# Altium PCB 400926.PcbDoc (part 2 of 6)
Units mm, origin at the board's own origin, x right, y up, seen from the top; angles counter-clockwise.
Board outline 148.5 x 63.5 mm, 4 copper layers (Top Layer, Mid-Layer 1, Mid-Layer 2, Bottom Layer), stack 1.514 mm thick; 311 components, 281 nets, 1495 pads, 2232 vias.
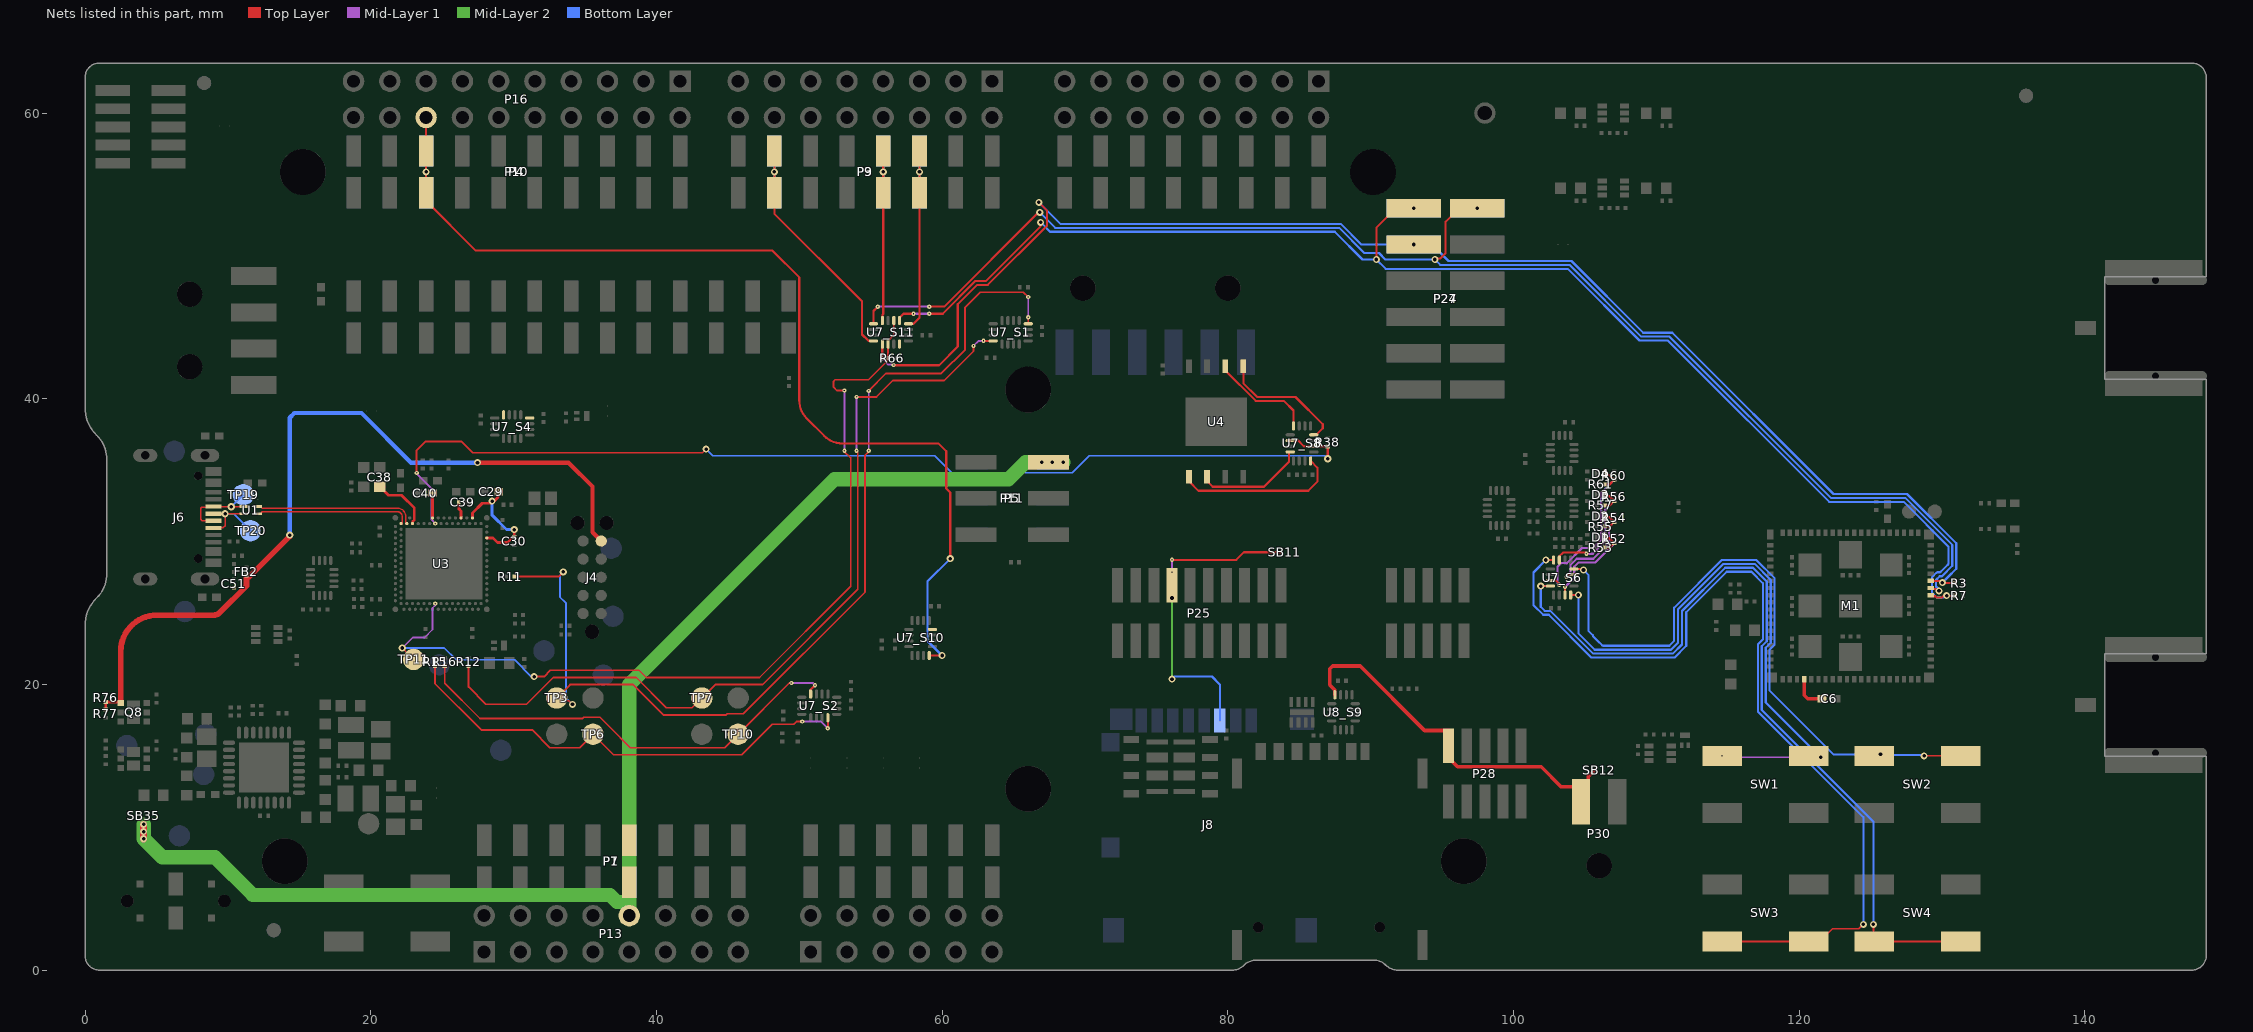
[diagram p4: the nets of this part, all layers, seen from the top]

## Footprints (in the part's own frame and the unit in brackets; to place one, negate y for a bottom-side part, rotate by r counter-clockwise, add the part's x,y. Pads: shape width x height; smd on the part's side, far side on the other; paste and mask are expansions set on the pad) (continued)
SOCKET_1x6_SMD [mm] "Socket, 2.54mm, SMD"
  rect 1.02x2.19 smd: 1(0,-1.465) 1(0,1.465) 2(2.54,-1.465) 2(2.54,1.465) 3(5.08,-1.465) 3(5.08,1.465) 4(7.62,-1.465) 4(7.62,1.465) 5(10.16,-1.465) 5(10.16,1.465) 6(12.7,1.465) 6(12.7,-1.465)
  silkscreen extent -1.27,-1.27 13.97,1.27, body extent -1.27,-2.29 13.97,2.29, height 7.47
SOCKET_1x8_SMD [mm] "Socket, 2.54mm, SMD"
  rect 1.02x2.19 smd: 1(0,-1.465) 1(0,1.465) 2(2.54,-1.465) 2(2.54,1.465) 3(5.08,-1.465) 3(5.08,1.465) 4(7.62,-1.465) 4(7.62,1.465) 5(10.16,-1.465) 5(10.16,1.465) 6(12.7,1.465) 6(12.7,-1.465) 7(15.24,-1.465) 7(15.24,1.465) 8(17.78,-1.465) 8(17.78,1.465)
  silkscreen extent -1.27,-1.27 19.05,1.27, body extent -1.27,-2.29 19.05,2.29, height 7.47
SOCKET_1x10_SMD [mm] "Socket, 2.54mm, SMD"
  rect 1.02x2.19 smd: 1(0,1.465) 1(0,-1.465) 2(2.54,-1.465) 2(2.54,1.465) 3(5.08,-1.465) 3(5.08,1.465) 4(7.62,-1.465) 4(7.62,1.465) 5(10.16,-1.465) 5(10.16,1.465) 6(12.7,-1.465) 6(12.7,1.465) 7(15.24,-1.465) 7(15.24,1.465) 8(17.78,-1.465) 8(17.78,1.465) 9(20.32,-1.465) 9(20.32,1.465) 10(22.86,-1.465) 10(22.86,1.465)
  silkscreen extent -1.27,-1.27 24.13,1.27, body extent -1.27,-2.29 24.13,2.29, height 7.47
SOCKET_2x3_SMD-2.54mm-NC [mm] "Socket, 2.54mm, SMD"
  rect 1.02x2.22 smd: 1(2.54,-2.825) 2(2.54,2.825) 3(0,-2.825) 4(0,2.825) 5(-2.54,-2.825) 6(-2.54,2.825)
  silkscreen extent -3.81,-3.3 3.81,2.54
SOCKET_2x6_SMD-2.54mm#1 [mil]
  rect 50x150 smd: 1(-250,-87.5) 2(-250,87.5) 3(-150,-87.5) 4(-150,87.5) 5(-50,-87.5) 6(-50,87.5) 7(50,-87.5) 8(50,87.5) 9(150,-87.5) 10(150,87.5) 11(250,-87.5) 12(250,87.5)
  silkscreen extent -310,-127 300,100, body extent -300,-138 300,139, height 290
SOCKET_2x6_SMD-2.54mm#2 [mil] "Board-Board Conn, Header, 4-way, 2-row"
  rect 50x150 smd: 1(-250,87.5) 2(-250,-87.5) 3(-150,87.5) 4(-150,-87.5) 5(-50,87.5) 6(-50,-87.5) 7(50,87.5) 8(50,-87.5) 9(150,87.5) 10(150,-87.5) 11(250,87.5) 12(250,-87.5)
  silkscreen extent -310,-100 300,127
SODFL35X40-2N [mm] "SODFL, 2-Leads, Body 0,60x0,35mm, IPC Medium Density"
  rect 0.25x0.6 smd: 1(-0.325,0) 3(0.325,0)
  body extent -0.53,-0.33 0.53,0.33, height 0.4
Solderbridge [mil]
  round 1 smd paste-99999: 1(-13.78,0) 2(13.78,0)
  Top Layer region: -7.49,19.36 -15.76,15.74 -21.55,8.8 -23.62,0 -23.62,0 -21.55,-8.79 -15.76,-15.74 -7.49,-19.36 -7.49,-19.36 -6.18,-19.31 -5.02,-18.71 -4.22,-17.68 -3.94,-16.4 -3.94,-16.4 -3.94,16.4 -4.22,17.68 -5.02,18.71 -6.18,19.31 -7.49,19.36
  Top Layer region: 7.49,-19.36 15.76,-15.74 21.55,-8.8 23.62,0 23.62,0 21.55,8.79 15.76,15.74 7.49,19.36 7.49,19.36 6.18,19.31 5.02,18.71 4.22,17.68 3.94,16.4 3.94,16.4 3.94,-16.4 4.22,-17.68 5.02,-18.71 6.18,-19.31 7.49,-19.36
Solderbridge_Shorted [mil]
  round 1 smd paste-99999: 1(-13.78,0) 2(13.78,0)
  Top Layer region: -4.92,3.94 -4.92,-3.94 4.92,-3.94 4.92,3.94
  Top Layer region: -7.49,19.36 -15.76,15.74 -21.55,8.8 -23.62,0 -23.62,0 -21.55,-8.79 -15.76,-15.74 -7.49,-19.36 -7.49,-19.36 -6.18,-19.31 -5.02,-18.71 -4.22,-17.68 -3.94,-16.4 -3.94,-16.4 -3.94,16.4 -4.22,17.68 -5.02,18.71 -6.18,19.31 -7.49,19.36
  Top Layer region: 7.49,-19.36 15.76,-15.74 21.55,-8.8 23.62,0 23.62,0 21.55,8.79 15.76,15.74 7.49,19.36 7.49,19.36 6.18,19.31 5.02,18.71 4.22,17.68 3.94,16.4 3.94,16.4 3.94,-16.4 4.22,-17.68 5.02,-18.71 6.18,-19.31 7.49,-19.36
Solderbridge_Shorted_Power [mil]
  round 1 smd paste-99999: 1(-13.84,0.21) 2(13.72,0.21)
  Top Layer region: -4.92,9.84 4.92,9.84 4.92,-9.84 -4.92,-9.84
  Top Layer region: 7.43,-19.16 15.71,-15.53 21.49,-8.59 23.56,0.21 23.56,0.21 21.49,9 15.71,15.94 7.43,19.57 7.43,19.57 6.12,19.52 4.96,18.92 4.16,17.89 3.88,16.61 3.88,16.61 3.88,-16.2 4.16,-17.47 4.96,-18.51 6.12,-19.11 7.43,-19.16
  Top Layer region: -7.54,19.57 -15.82,15.94 -21.61,9 -23.68,0.21 -23.68,0.21 -21.61,-8.59 -15.82,-15.53 -7.54,-19.16 -7.54,-19.16 -6.24,-19.11 -5.08,-18.51 -4.28,-17.47 -4,-16.2 -3.99,-16.2 -3.99,16.61 -4.28,17.89 -5.08,18.92 -6.24,19.52 -7.54,19.57
SON50P210X160X65_HS-9N [mm] "SON, 8-Leads, Body 2.10x1.60mm, Pitch 0.50mm, Thermal Pad 1.70x0.4mm, IPC Medium Density"
  rect 0.7x0.25 smd mask+0.05: 1(-0.725,0.75) 2(-0.725,0.25) 3(-0.725,-0.25) 4(-0.725,-0.75) 5(0.725,-0.75) 6(0.725,-0.25) 7(0.725,0.25) 8(0.725,0.75)
  rect 0.4x1.7 smd paste-2 mask+0.05: 9(0,0)
  rect 0.3x0.75 on Top Paste: ""(0,0.425) ""(0,-0.425)
  silkscreen extent -1.26,1.2 -1.16,1.26, body extent -0.85,-1.1 0.85,1.1, height 0.65
SON127P600X90_HS-8N [mm] "SON, 8-Leads, Body 5.00x6.00mm, Pitch 1.27mm, IPC Medium Density"
  rect 1.5x0.35 smd paste-1.27: 0(-0.95,-1.73) 0(-0.95,1.73) 0(0.95,-1.73) 0(0.95,1.73)
  rect 1.5x0.7 smd paste-1.27: 0(-0.95,-0.635) 0(-0.95,0.635) 0(0.95,-0.635) 0(0.95,0.635)
  rect 1.1x0.5 smd paste-1.27: 1(-2.75,1.905) 2(-2.75,0.635) 3(-2.75,-0.635) 4(-2.75,-1.905) 5(2.75,-1.905) 6(2.75,-0.635) 7(2.75,0.635) 8(2.75,1.905)
  silkscreen extent -3.6,-2.58 3.08,2.72, body extent -3,-2.5 3,2.5, height 0.65
SON127P800X80_HS-9N [mm] "SON, 8-Leads, Body 6.00x8.00mm, Pitch 1.27mm, Thermal Pad 4.30x3.40mm, IPC Medium Density"
  rect 0.95x0.4 smd: 1(-3.87,1.905) 2(-3.87,0.635) 3(-3.87,-0.635) 4(-3.87,-1.905) 5(3.87,-1.905) 6(3.87,-0.635) 7(3.87,0.635) 8(3.87,1.905)
  rect 3.4x4.3 smd paste-1.7: 9(0,0)
  silkscreen extent -4.52,-3.18 4.18,3.52, body extent -4.05,-3.05 4.05,3.05, height 0.8
SOTFL50P162X60-6N [mm] "SOTFL, 6-Leads, Body 1.60x1.63mm, Pitch 0.50mm, IPC Medium Density"
  rect 0.65x0.35 smd: 1(-0.775,0.5) 2(-0.775,0) 3(-0.775,-0.5) 4(0.775,-0.5) 5(0.775,0) 6(0.775,0.5)
  silkscreen extent -0.9,-0.82 0.05,1.35, body extent -0.81,-0.85 0.81,0.85, height 0.6
TC2050-IDC-NLFP [mil]
  round 39 hole 39 unplated: 0(-150,0) 0(150,-40) 0(150,40)
  round 31 smd paste-196.85: 1(-100,-25) 2(-50,-25) 3(0,-25) 4(50,-25) 5(100,-25) 6(100,25) 7(50,25) 8(0,25) 9(-50,25) 10(-100,25)
  Top Layer pour cut-out: -100,25 -100,-25 100,-25 100,25
TESTPAD-TH [mm]
  round 1.5 hole 1: 1(0,0)
TP_SMD_D1.0mm [mm] "Test point - pad 1.0mm"
  round 1 smd paste-5: 1(0,0)
TP_SMD_D1.5mm [mm] "Test point - pad 1.5mm"
  round 1.5 smd paste-5: 1(0,0)
  body extent -0.75,-0.75 0.75,0.75, height 0.05
UFDFN50P120X250X55-8N [mm]
  round 0.025 smd: 1(-0.5,0.75) 4(-0.5,-0.75) 5(0.5,-0.75) 8(0.5,0.75)
  rect 0.6x0.2 smd: 2(-0.5,0.25) 3(-0.5,-0.25) 6(0.5,-0.25) 7(0.5,0.25)
  Top Layer region: -0.2,0.65 -0.8,0.65 -0.8,0.85 -0.4,0.85 -0.4,1.05 -0.2,1.05
  Top Layer region: 0.4,0.85 0.8,0.85 0.8,0.65 0.2,0.65 0.2,1.05 0.4,1.05
  Top Layer region: -0.2,-1.05 -0.4,-1.05 -0.4,-0.85 -0.8,-0.85 -0.8,-0.65 -0.2,-0.65
  Top Layer region: 0.8,-0.85 0.4,-0.85 0.4,-1.05 0.2,-1.05 0.2,-0.65 0.8,-0.65
  silkscreen extent -1.08,1.21 -0.95,1.33, body extent -0.6,-1.25 0.6,1.25, height 0.6
WEEE_3x4.5mm [mm]
  silkscreen extent -1.47,-2.7 1.47,1.71
XQFN40P180X260X50-16N [mm] "QFN, 16-Leads, Body 1.80x2.60mm, Pitch 0.40mm, IPC Medium Density"
  oval 0.65x0.22 smd paste-0.02 mask+0.04: 1(-0.825,0.6) 2(-0.825,0.2) 3(-0.825,-0.2) 4(-0.825,-0.6) 9(0.825,-0.6) 10(0.825,-0.2) 11(0.825,0.2) 12(0.825,0.6)
  oval 0.22x0.65 smd paste-0.02 mask+0.04: 5(-0.6,-1.225) 6(-0.2,-1.225) 7(0.2,-1.225) 8(0.6,-1.225) 13(0.6,1.225) 14(0.2,1.225) 15(-0.2,1.225) 16(-0.6,1.225)
  body extent -0.91,-1.31 0.91,1.31, height 0.55

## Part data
C1 C2: library part C0201-1µ0-10V-X5R-GRM033R61A105ME15, "Capacitor, X5R, ±20%, 10V", Manufacturer=Murata, Manufacturer Part Number=GRM033R61A105ME15, Part number IPS=N.A., Part number NEMS=100200545, Supplier Part Number 1=490-13226-1-ND
C3 C7: library part C0603-10µ-10V-X6S-GRM188C81A106MA73, "Capacitor, Ceramic, 10µF 10V X6S 0603,±20%", Manufacturer=Murata, Manufacturer Part Number=GRM188C81A106MA73, Part number IPS=N.A., Part number NEMS=100200520, Supplier Part Number 1=490-7197-2-ND
C4 C8 C10 C24 C25 C26 C27 C31 C32 C33 C34 C39 C42 C43 C51 C52_S1 C52_S2 C52_S3 C52_S4 C52_S5 C52_S6 C52_S8 C52_S10 C52_S11 C53_S7 C53_S9 C62: library part C0201-100n, "Capacitor, X5R, ±10%, 100nF, 16V", Manufacturer=N.A., Part number IPS="00000001248, 00000002505", Part number NEMS=100200078, Part number Norautron=262071862
C5 C6: library part C0402-4µ7-10V-X5R, "Capacitor, X5R, 10V", Manufacturer=Murata, Manufacturer Part Number=GRM155R61A475MEAAD, Part number IPS=N.A., Part number NEMS=100200415, Supplier Part Number 1=490-14306-1-ND
C9: library part C0402-1µ0-16V-X5R, "Capacitor, Ceramic, X5R, ±10%, 16V", Manufacturer=Murata, Manufacturer Part Number=GRT155R61C105KE01D, Part number IPS=N.A., Part number NEMS=100200452, Supplier Part Number 1=490-12255-1-ND
C11 C12: library part C0201-39p, "Capacitor, NP0, ±1%, 25V", Manufacturer=Murata, Manufacturer Part Number=GRM0335C1E390FA01D, Part number IPS=00000001668, Part number NEMS=100200039, Part number Norautron=N.A.
C19 C49: library part C0201-N.C., "Not mounted", Manufacturer=N.A., Part number NEMS=100200001
C28 C29 C35 C36 C40 C64: library part C0402-1µ0-10V-X5R, "Capacitor, Ceramic, X5R, ±10%, 10V", Manufacturer=N.A., Part number NEMS=100200482
C30: library part C0201-2n2, "Capacitor, X7R, ±10%, 10V", Manufacturer=N.A., Part number IPS=00000001778, Part number NEMS=100200060, Part number Norautron=26470002
C37 C38 C58: library part C0603-4µ7-10V-X5R, "Capacitor, Ceramic, X5R, ±10%, 10V", Manufacturer=N.A., Part number NEMS=100200479, Part number Norautron=262081761
C41 C48 C50: library part C0201-10n, "Capacitor, X7R, ±10%, 10nF, 10V", Manufacturer=N.A., Part number IPS=00000003480, Part number NEMS=100200067, Part number Norautron=26621779
C44 C45 C46 C47: library part C0201-1µ0, "Capacitor, X5R, ±10%", Manufacturer=N.A., Part number IPS=00000001723, Part number NEMS=100200084, Supplier Part Number 1=1276-6795-1-ND
C54: library part C0603-1µ0-10V-X5R, "Capacitor, Ceramic, 1.0µF 10V X5R 0603,±10%", Manufacturer=N.A., Part number NEMS=100200528
C55 C56 C57 C59 C60: library part C0603-10µ-10V-X7T-GRM188D71A106MA73, "Capacitor, X7T, ±20%, 10V", Manufacturer=Murata, Manufacturer Part Number=GRM188D71A106MA73D, Part number IPS=00000004696, Part number NEMS=100200414, Part number Norautron=N.A., Supplier Part Number 1=490-7200-1-ND
C61 C63: library part C0402-10n, "Capacitor, X7R, ±10%", Manufacturer=N.A., Part number IPS=00000007784, Part number NEMS=100200173
C65 C66 C67: library part C0201-1n0, "Capacitor, X7R, ±10%, 25V", Manufacturer=N.A., Part number IPS=00000003206, Part number NEMS=100200056
C68 C69 C71: library part C0603-N.C., "Not mounted", Manufacturer=N.A., Part number NEMS=100200195
C70 C72: library part C0603-100n, "Chip Cap 0603", Manufacturer=N.A., Part number NEMS=100200265
D1 D2 D3 D4: "DIODE SCHOTTKY 20V 500MA SOD882", Manufacturer="Central Semiconductor Corp.", Part number IPS=00000002493, Part number NEMS=101300101, Part number Norautron=N.A., Supplier Part Number 1="CFSH05-20L CT-ND"
D5: "ESD Protection and EMI Filter for SIM Card Interface", Manufacturer="Texas Instruments", Part number IPS=N.A., Part number NEMS=101900729, Supplier Part Number 1=296-28299-1-ND
FB1: library part FB0603-22R@100MHz-6000mA, "Ferrite Bead, 22 Ohm @ 100MHz, 6000mA, 8 mOhm Max", Manufacturer=Murata, Manufacturer Part Number=BLM18SD220SN1D, Part number IPS=N.A., Part number NEMS=100300492, Supplier Part Number 1=490-15633-2-ND
FB2: library part FB0201-120R@100M-900mA-BLM03PX121SN1D, "Ferrite Bead, 120 Ohm @ 100MHz, 900mA, 160 mOhm Max", Manufacturer=Murata, Manufacturer Part Number=BLM03PX121SN1D, Part number IPS=N.A., Part number NEMS=100300405, Supplier Part Number 1=490-BLM03PX121SN1DTR-ND
FB4 FB5 FB6: library part R0805-0R, "Resistor, ±5%, 0.125W", Manufacturer=N.A., Part number NEMS=100100375
Fid1 Fid2 Fid3: library part Fid-Mark, "Fiducial Mark", Manufacturer=N.A., Part number NEMS=100500073
J1 J2: library part SMA-Edge-C02AJ3F64B-1, "SMA Jack, Female, 50 Ohm, Board Edge, Cutout, SMT", Manufacturer="Wellshow Technology", Manufacturer Part Number=C02AJ3F64B-1, Part number IPS=N.A., Part number NEMS=100500896
J4: library part TC2050-IDC-NLFP, "CBL PLUG-OF-NAILS 10-PIN", Manufacturer="Tag-Connect LLC", Part number IPS=N.A., Part number NEMS=100500463, Supplier Part Number 1=TC2050-IDC-NL-ND
J5: library part L-KLS1-SIM-066-(6+1)P-H1.37-R, "Nano SIM Card Connector, Push-Push, 6-Pin, H1.37mm, with CD Pin", Manufacturer="KLS Electronic", Part number IPS=N.A., Part number NEMS=100500776
J6: library part 80259-1021, "USB-C Receptacle, 16 Pin, USB 2.0", Manufacturer="Bellweather Electronic Corp.", Part number IPS=N.A., Part number NEMS=100500830
J8: library part Molex_502774-0891, "1.10mm Pitch microSD Memory Card Connector, Reverse Mount Surface Mount, Push-Push Type", Manufacturer=Molex, Manufacturer Part Number=502774-0891, Part number IPS=00000001284, Part number NEMS=100500509, Part number Norautron=N.A., Supplier Part Number 1=WM24066CT-ND
L3: library part L0402-68n-Wirewound-Murata, "Inductor, 140mA, ±2%, 1960mΩ, Q=20", Manufacturer=Murata, Manufacturer Part Number=LQW15AN68NG00, Part number IPS=00000002494, Part number NEMS=100300389, Part number Norautron=N.A., Supplier Part Number 1=490-6837-1-ND
L4: library part L0402-N.C., "Not mounted", Manufacturer=N.A., Part number NEMS=100300037
L7 L8: library part L0806-2µ2-2500mA-73mOhm-CIGT201610EH2R2MNE, "Inductor, Irms=2.5A, Isat=2.9A, ±20%, DCR=73mΩ", Manufacturer="Samsung Electro-Mechanics America", Manufacturer Part Number=CIGT201610EH2R2MNE, Part number IPS=N.A., Part number NEMS=100300400, Part number Norautron=26521789, Supplier Part Number 1=1276-6901-1-ND
LABEL1: library part Label_15x40, "PCA version label, stick-on, 15x40mm", Manufacturer="Ellco Etikett", Manufacturer Part Number=51945, Part number IPS=N.A., Part number NEMS=101200030
LED1 LED2 LED3 LED4 LED5: library part "VS 25C7M5", "LED, Green, 0603, 573nm, Vf=2.0V, 24mcd, - 40 to +85°C", Manufacturer="Victory Electronics", Part number IPS="00000001274, 00000009961", Part number NEMS=101400097, Part number Norautron=26313411, Supplier Part Number 1=N.A.
LOGO1: library part "WEEE Symbol 3x4.5mm", "WEEE Directive symbol", Manufacturer=N.A., Part number NEMS=101100006
LOGO2: "Segger logo, small size", Manufacturer=N.A., Part number NEMS=101100004
LOGO3: library part "Nordic Logo lying", "Nordic logo lying", Manufacturer=N.A., Part number NEMS=101100001
M1: "Low power System-in-Package with integrated LTE-M/NB-IoT modem and GPS", Manufacturer="Nordic Semiconductor", Part number IPS=N.A., Part number NEMS=102000407
P1 P3 P6: library part "Socket 1x8 SMD", "Socket 1x8, 2.54mm (100mil), SMD", Manufacturer=WCON, Manufacturer Part Number=2171-108MS0CUNR3, Part number IPS=N.A., Part number NEMS=100500412
P2: library part "Socket 1x6 SMD", "Socket 1x6, 2.54mm (100mil), SMD", Manufacturer=WCON, Manufacturer Part Number=2171-106MS0CUNR3, Part number IPS=N.A., Part number NEMS=100500408
P4: library part "Socket 1x10 SMD", "Socket 1x10, 2.54mm (100mil), SMD", Manufacturer=WCON, Manufacturer Part Number=2171-110MS0CUNR3, Part number IPS=N.A., Part number NEMS=100500416
P5: library part "Pin Header 2x3 SMD", "Pin Header 2x3, 2.54mm (100mil) SMD", Manufacturer=WCON, Manufacturer Part Number=1125-1203S0M116CR03, Part number IPS=N.A., Part number NEMS=100500242
P7 P9 P12: library part "Pin List 1x8 SMD, N.C.", "Pin List 1x8, 2.54mm (100mil), SMD", Manufacturer=WCON, Manufacturer Part Number=1125-1108S0M116CR04, Part number IPS=N.A., Part number NEMS=100500330
P8: library part "Pin List 1x6 SMD, N.C.", "Pin List 1x6, 2.54mm (100mil), SMD", Manufacturer=WCON, Manufacturer Part Number=1125-1106S0M116CR06, Part number IPS=N.A., Part number NEMS=100500321
P10: library part "Pin List 1x10 SMD, N.C.", "Pin List 1x10, 2.54mm (100mil), SMD", Manufacturer=WCON, Manufacturer Part Number=1125-1110S0M116CR06, Part number IPS=N.A., Part number NEMS=100500338
P11: library part "Socket 2x3 SMD, N.C.", "Socket 2x3, 2.54mm (100mil), SMD", Manufacturer=WCON, Manufacturer Part Number=2171-203MS0CUNR3, Part number IPS=N.A., Part number NEMS=100500434
P13 P15 P17: library part "Pin Header 2x8, N.C.", "Pin Header 2x8, 2.54mm (100mil)", Manufacturer=N.A., Part number NEMS=100500270
P14: library part "Pin Header 2x6, N.C.", "Pin Header 2x6, 2.54mm (100mil)", Manufacturer=N.A., Part number NEMS=100500265
P16: library part "Pin Header 2x10, N.C.", "Pin Header 2x10, 2.54mm (100mil)", Manufacturer=N.A., Part number NEMS=100500274
P18 P19: library part "Pin Header 2x5 SMD, 1.27mm, KS", "Pin Header 2x5, 1.27mm (50mil), SMD, Keying Shroud", Manufacturer=WCON, Manufacturer Part Number=3132-10MS0BK00R5, Part number IPS=N.A., Part number NEMS=100500261
P20: library part "Pin List 1x13 SMD", "Pin List 1x13, 2.54mm (100mil), SMD", Manufacturer=WCON, Manufacturer Part Number=1125-1113S0M116CR04, Part number IPS=N.A., Part number NEMS=100500345
P22: library part "Pin List Ang 1x4 SMD, 2.54mm", "Pin List 1x4, 2.54mm (100mil), Right Angled, SMD", Manufacturer=WCON, Manufacturer Part Number=1125B-1104S0Z135CR04, Part number IPS=N.A., Part number NEMS=100500358
P24 P27: library part "Socket 2x6 SMD", "Socket 2x6, 2.54mm (100mil), SMD", Manufacturer=WCON, Manufacturer Part Number=2171-206MS0CUNR3, Part number IPS=N.A., Part number NEMS=100500439
P25: library part "Pin Header 2x10 SMD, 1.27mm, KS, SWD (Cabcon)", "Pin Header 2x10, 1.27mm (50mil), SMD, Keying Shroud, Removed Pin 7", Manufacturer=WCON, Manufacturer Part Number=3132-20MS0BK00R5, Part number IPS=N.A., Part number NEMS=100500841,100500280
P26: library part "Socket 1x13 SMD, N.C.", "Socket 1x13, 2.54mm (100mil), SMD", Manufacturer=WCON, Manufacturer Part Number=2171-113MS0CUNR1, Part number IPS=N.A., Part number NEMS=100500422
P28: library part "Pin Header 2x5 SMD, 1.27mm", "Pin Header 2x5, 1.27mm (50mil), SMD", Manufacturer=WCON, Manufacturer Part Number=1325-1205S0M078CR03, Part number IPS=N.A., Part number NEMS=100500259
P29: library part "Pin List Ang 1x6 SMD, 2.54mm", "Pin List 1x6, 2.54mm (100mil), Right Angled, SMD", Manufacturer=N.A., Part number IPS=00000003922, Part number NEMS=100500362, Supplier Part Number 1=TSM-106-01-L-SH-A
P30: library part "Pin List Ang 1x2 SMD, 2.54mm", "Pin List 1x2, 2.54mm (100mil), Right Angled, SMD", Manufacturer=WCON, Manufacturer Part Number=1125B-1102S0Z135CR06, Part number IPS=N.A., Part number NEMS=100500354
Q1 Q7: "Dual N & P Ch MOFET, 1.03A/0.7A, 480mOhm, 450mW", Manufacturer="Diodes Incorporated", Part number IPS=00000007803, Part number NEMS=101300117, Part number Norautron=N.A., Supplier Part Number 1=DMC2400UV-7DICT-ND
Q2 Q3 Q6: "N-Channel MOSFET, 20V, 1A, 470mOhm, 400mW, -55°C ~ 150°C", Manufacturer="Rohm Semiconductor", Part number IPS=00000009976, Part number NEMS=101300132, Part number Norautron=26320026, Supplier Part Number 1=RV2C010UNT2LCT-ND
Q4 Q5: "Dual N-Channel MOSFET, Vds = 30V, Vgs(th) = 1.5V, Id = 0.5A, Rds = 750mOhm, Pd = 150mW, -55°C ~ 150°C", Manufacturer="Micro Commercial Components", Manufacturer Part Number=UM6X1NA-TP, Part number IPS=N.A., Part number NEMS=101300201, Supplier Part Number 1=353-UM6X1NA-TPCT-ND
Q8 Q9: "Dual P-Channel MOFET, 3.8A, 90mOhm max, 1.4W", Manufacturer="Micro Commercial Components", Part number IPS=N.A., Part number NEMS=101300199, Supplier Part Number 1=MCM2301-TPMSCT-ND
R1 R8 R77 R79: library part R0201-10k, "Resistor, ±1%, 0.05W", Manufacturer=N.A., Part number IPS=00000001255, Part number NEMS=100100065, Part number Norautron=26107101
R2: library part R0201-1k0, "Resistor, ±1%, 0.05W", Manufacturer=N.A., Part number IPS=00000005786, Part number NEMS=100100043
R3 R7 R13 R14 R17 R18 R24 R31 R32 R38 R43 R44 R45 R46 R47 R62 R66 R67 R69 R72 R73 R75 R80: library part R0201-1M0, "Resistor, ±1%, 0.05W", Manufacturer=N.A., Part number IPS=00000001418, Part number NEMS=100100093, Part number Norautron=26107108
R9 R23 R59: library part R0201-N.C., "Not mounted", Manufacturer=N.A., Part number NEMS=100100107
R10 R34 R35 R52 R54 R56 R60 R63 R64 R65 R76 R81 R85 R86: library part R0201-100k, "Resistor, ±1%, 0.05W", Manufacturer=N.A., Part number IPS=00000001419, Part number NEMS=100100080, Part number Norautron=26108487
R11 R12 R15 R16 R19 R20 R22 R25 R26 R27 R28 R29 R30: library part R0201-150, "Resistor, ±1%, 0.05W", Manufacturer=N.A., Part number IPS=00000001420, Part number NEMS=100100029
R21: library part R0201-2R2, "Resistor, ±1%, 0.05W", Manufacturer=N.A., Part number NEMS=100100006, Part number Norautron=26470029
R33 R39 R40 R41 R42: library part R0201-120, "Resistor, ±1%, 0.05W", Manufacturer=N.A., Part number IPS=00000000880, Part number NEMS=100100028, Part number Norautron=26107076
R36 R74: library part R0201-47k, "Resistor, ±1%, 0.05W", Manufacturer=N.A., Part number IPS=00000001423, Part number NEMS=100100076
R37 R78: library part R0201-150k, "Resistor, ±1%, 0.05W", Manufacturer=N.A., Part number IPS=00000001422, Part number NEMS=100100082
R48 R49 R83 R84: library part R0201-4k7, "Resistor, ±1%, 0.05W", Manufacturer=N.A., Part number IPS=00000001706, Part number NEMS=100100061
R50 R51: library part R0201-12k, "Resistor, ±1%, 0.05W", Manufacturer=N.A., Part number IPS=00000007891, Part number NEMS=100100066, Part number Norautron=26192279
R53 R55 R57 R61: library part R0201-18k, "Resistor, ±1%, 0.05W", Manufacturer=N.A., Part number IPS=00000001707, Part number NEMS=100100069
R58 R87: library part R0201-0R, "Resistor, ±5%, 0.05W", Manufacturer=N.A., Part number IPS=00000003245, Part number NEMS=100100001
R68: library part R0201-1k87, "Resistor, ±1%, 0.05W", Manufacturer=N.A., Part number NEMS=100100050
R70 R71: library part R0201-5k1, "Resistor, ±1%, 0.05W", Manufacturer=N.A., Part number NEMS=100100565, Part number Norautron=26192285
R82: library part R0402-N.C., "Not mounted", Manufacturer=N.A., Part number NEMS=100100281
SB3 SB4 SB5 SB6 SB7 SB8 SB9 SB10 SB14 SB17 SB18 SB21 SB23 SB24 SB25 SB28 SB32: library part "Solderbridge Shorted", "Shorted Solderbridge", Manufacturer=N.A., Part number NEMS=100500459
SB11 SB12 SB13 SB15 SB16 SB19 SB20 SB22 SB26 SB27 SB29 SB34: Manufacturer=N.A., Part number NEMS=100500458
SB30 SB31 SB33 SB35: library part "Solderbridge Shorted Power", "Shorted Solderbridge Power", Manufacturer=N.A., Part number NEMS=100500460
SW1 SW2 SW3 SW4 SW5: library part L-KLS7-TS6616B-2.5-160-T, "Tactile Switch, SPNO, SMD, 160gf, 6.2x6.4x2.5mm", Manufacturer=KLS, Part number IPS=N.A., Part number NEMS="101500133, 101500001"
SW6: library part Switch-Slide-RA-J-Lead-DPDT-8.5x3.5mm_C&K, "SMD slide Switch (ON-ON)", Manufacturer=C&K, Manufacturer Part Number=JS202011JAQN, Part number IPS=00000007811, Part number NEMS=101500037, Part number Norautron=N.A., Supplier Part Number 1=CKN10722CT-ND
TP1 TP2: library part TP_SMD_Ø1.0MM, "1.0mm circular SMD testpad", Manufacturer="Nordic Semiconductor", Manufacturer Part Number=N.A., Part number NEMS=100500475
TP3 TP4 TP5 TP6 TP7 TP8 TP9 TP10 TP11 TP12 TP13 TP14 TP15 TP16 TP17 TP18 TP19 TP20 TP21 TP22 TP23 TP25 TP26 TP27: library part TP_SMD_Ø1.5MM, "1.5mm circular SMD testpad", Manufacturer="Nordic Semiconductor", Manufacturer Part Number=N.A., Part number NEMS=100500477
TP24: library part "Testpoint TH", "Testpoint, through hole", Manufacturer=N.A., Part number NEMS=100500464
U1: "2 Line Common mode filter with ESD protection for USB 2.0 interface, DCRmax = 4Ohm, -40°C ~ 125°C", Manufacturer=STMicroelectronics, Part number IPS=N.A., Part number NEMS=100800034, Supplier Part Number 1=497-13420-2-ND
U3: library part nRF5340-QKAAD0, "Multi-protocol Bluetooth Low Energy, IEEE 802.15.4, ANT and 2.4GHz proprietary system-on-chip", Manufacturer="Nordic Semiconductor", Part number IPS=N.A., Part number NEMS=102000216, Part number Norautron=NOD26470035
U4: library part GD25WB256EYIGR, "Quad Serial Flash, 256Mbit, 104MHz, 1.65V - 3.6V", Manufacturer=GigaDevice, Part number IPS=N.A., Part number NEMS=101900774
U5: library part PCAL6408AHK, "8-bit I2C-bus I/O expander with interrupt output", Manufacturer="NXP Semiconductors", Part number IPS=00000009987, Part number NEMS=101900289, Part number Norautron=N.A., Supplier Part Number 1=568-9944-1-ND
U6: library part M2M_UICC, "M2M UICC SIM Card", Manufacturer=N.A., Part number NEMS=101900595
U7_S1 U7_S2 U7_S3 U7_S4 U7_S5 U7_S6 U7_S8 U7_S10 U7_S11: "Data / Audio Low-Voltage Dual DPDT Analog Switch", Manufacturer="ON Semiconductor", Part number IPS=00000009986, Part number NEMS=101900422, Part number Norautron=26500608, Supplier Part Number 1=FSA2466UMXCT-ND
U8_S7 U8_S9: library part NX3DV2567GU, "Low-ohmic four-pole double-throw analog switch", Manufacturer="NXP Semiconductors", Part number IPS=00000007816, Part number NEMS=101900290, Part number Norautron=N.A., Supplier Part Number 1=568-5206-1-ND
U9: "Li-Ion/Li-Polymer USB-C battery charger with high efficiency buck regulators, LDOs or load switches, LED drivers, TWI and VBUSOUT", Manufacturer="Nordic Semiconductor", Part number IPS=N.A., Part number NEMS=102000291
X1: library part XTAL_SMD2016_32MHz_8pF_Kyocera, "XTAL SMD 2016, 32MHz, Cl=8pF, Tot: ±40ppm", Manufacturer=Kyocera, Manufacturer Part Number=CX2016DB32000D0WZRC1, Part number IPS=00000007827, Part number NEMS=101600039, Part number Norautron=26511136, Supplier Part Number 1=1253-1586-1-ND
Y1 Y2: library part "SHUNT JUMPER 2.54mm Black Tin", "Shunt Jumper 2.54mm Black, open top", Manufacturer=WCON, Manufacturer Part Number=3710-6001OS0B05, Part number IPS=N.A., Part number NEMS=100500728

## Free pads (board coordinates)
  round 3.2 hole 3.2 unplated: 1(13.97,7.62) 1(15.24,55.88) 1(66.04,12.7) 1(66.04,40.64) 1(90.17,55.88) 1(96.52,7.62)

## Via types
v1: diameter 0.5, hole 0.25, Top Layer to Bottom Layer, tented both sides, 1704 vias
v2: diameter 0.3, hole 0.1, Top Layer to Mid-Layer 1, tented top, 426 vias
v3: diameter 0.3, hole 0.1, Top Layer to Mid-Layer 1, tented both sides, 93 vias
v4: diameter 0.61, hole 0.305, Top Layer to Bottom Layer, tented both sides, 9 vias

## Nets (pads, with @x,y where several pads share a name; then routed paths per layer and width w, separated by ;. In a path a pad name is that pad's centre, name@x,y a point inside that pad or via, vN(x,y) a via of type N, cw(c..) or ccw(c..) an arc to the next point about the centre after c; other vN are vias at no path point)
5V: P1.5 P5.2 P7.5 P11.2 P13.10 SB35.2 | length 90.8
  Top Layer w0.5: v1(4.1,9.199) v1(4.1,9.699) v1(4.1,10.199)
  Mid-Layer 2 w1: v1(4.1,9.199) v1(4.1,9.699) v1(4.1,10.199) ; v1@4.107,9.192 5.4,7.899 9.1,7.899 11.748,5.251 36.748,5.251 37.235,4.764 38.1,4.764 ; P13.10@38.1,3.81 38.1,4.764 ; v1(68.472,35.56) v1(67.722,35.56) v1(66.972,35.56) 65.841,35.56 64.65,34.368 52.469,34.368 38.1,19.999 38.1,4.764
AREF: P4.8 P10.8 P16.16 U7_S10.8 | length 74.8
  Top Layer w0.15: P16.16@23.876,59.69 P4.8@23.876,57.345 v1(23.876,55.88) P4.8@23.876,54.415 23.876,53.848 27.356,50.368 39.539,50.368 39.541,50.367 40.825,50.367 40.826,50.368 48.131,50.368 50,48.499 50,39.886 ccw(c51.8,39.886) 50.524,38.616 51.742,37.399 ccw(c53.012,38.674) 53.012,36.874 59.742,36.874 60.294,36.321 60.294,33.716 60.569,33.441 v1(60.569,28.807) ; U7_S10.8@59.1,22.024 v1(60,22.024) v1@60.086,22.024
  Bottom Layer w0.15: P10.8@23.876,53.848 v1(23.876,55.88) P10.8@23.876,57.345 ; v1(60,22.024) 59.989,22.024 58.975,23.038 58.975,27.212 v1(60.569,28.807)
BTN1_EXT: D1.1 R52.1 R53.2 U7_S6.15 | length 7.3
  Top Layer w0.15: U7_S6.15@103.61,26.258 v2(103.61,26.824) ; R53.2@106.399,29.58 106.723,29.58 v2(107.048,29.905) 106.723,30.23 D1.1@106.399,30.23
  Mid-Layer 1 w0.15: v2(103.61,26.824) 104.26,27.474 104.26,28.235 104.548,28.524 105.71,28.524 107.048,29.862 v2(107.048,29.905)
BTN2_EXT: D2.1 R54.1 R55.2 U7_S6.3 | length 8
  Top Layer w0.15: v2(103.714,27.538) 103.859,27.683 U7_S6.3@104.235,27.683 ; R55.2@106.399,31.054 106.723,31.054 v2(107.048,31.378) 106.723,31.703 D2.1@106.399,31.703
  Mid-Layer 1 w0.15: v2(103.714,27.538) 103.985,27.809 103.985,28.349 104.435,28.799 105.596,28.799 106.698,29.901 106.698,31.028 v2(107.048,31.378)
BTN3_EXT: D3.1 R56.1 R57.2 U7_S6.7 | length 8.6
  Top Layer w0.15: U7_S6.7@103.21,28.708 103.21,28.961 103.481,29.233 104.646,29.233 104.652,29.227 105.032,29.227 v2(105.11,29.149) ; R57.2@106.399,32.527 106.723,32.527 v2(107.048,32.851) 106.723,33.176 D3.1@106.399,33.176
  Mid-Layer 1 w0.15: v2(105.11,29.149) 105.557,29.149 106.423,30.015 106.423,32.226 v2(107.048,32.851)
BTN4_EXT: D4.1 R60.1 R61.2 U7_S6.11 | length 12.1
  Top Layer w0.15: U7_S6.11@102.585,27.283 102.951,27.283 103.21,27.024 v2(103.21,26.974) ; R61.2@106.399,34 106.723,34 v2(107.048,34.325) 106.723,34.649 D4.1@106.399,34.649
  Mid-Layer 1 w0.15: v2(103.21,26.974) 103.085,27.099 103.085,28.228 103.348,28.492 103.721,28.492 103.73,28.483 104.802,29.555 105.574,29.555 106.148,30.129 106.148,33.425 v2(107.048,34.325)
BUTTON1: SW1.2 U7_S6.16 | length 42.6
  Top Layer w0.152: U7_S6.16@104.01,26.258 v1(104.547,26.258)
  Mid-Layer 1 w0.125: v2(114.6,14.999) 114.647,14.999 114.747,14.899 v1(121.5,14.899)
  Bottom Layer w0.15: v1(104.547,26.258) 104.547,23.575 105.694,22.427 111.028,22.427 111.525,22.924 111.525,25.255 114.708,28.437 116.889,28.437 118.012,27.314 118.012,22.912 117.662,22.562 117.662,18.736 v1(121.5,14.899)
BUTTON2: SW2.2 U7_S6.4 | length 45.6
  Top Layer w0.125: v1(128.75,14.999) SW2.2@130.665,14.999
  Top Layer w0.152: U7_S6.4@104.235,28.083 v1@104.904,28.083
  Bottom Layer w0.15: v1(104.904,28.008) 105.267,27.646 105.267,23.733 105.562,23.437 ccw(c105.687,23.438) 105.598,23.35 105.905,23.044 106.211,22.738 ccw(c106.299,22.827) 106.298,22.702 110.903,22.702 111.25,23.049 111.25,25.369 114.594,28.712 117.003,28.712 118.287,27.428 118.287,22.799 117.937,22.449 117.937,19.563 122.401,15.099 v1(125.7,15.099) 125.75,15.049 128.7,15.049 v1(128.75,14.999)
BUTTON3: SW3.2 U7_S6.8 | length 63.1
  Top Layer w0.125: SW3.2@114.815,1.999 SW3.2@120.665,1.999 121.45,1.999 122.337,2.886 124.187,2.886 v1(124.5,3.199)
  Top Layer w0.152: v1(102.273,28.708) U7_S6.8@102.81,28.708
  Bottom Layer w0.15: v1(102.273,28.708) 101.4,27.835 101.4,25.551 102.077,24.874 102.47,24.874 105.467,21.877 111.278,21.877 112.1,22.699 112.1,25.049 114.938,27.887 116.661,27.887 117.462,27.086 117.462,23.14 117.112,22.79 117.112,18.098 124.5,10.71 v1(124.5,3.199)
BUTTON4: SW4.2 U7_S6.12 | length 58.1
  Top Layer w0.125: SW4.2@125.115,1.999 125.2,2.084 v1(125.2,3.199) ; SW4.2@125.265,1.999 SW4.2@131.165,1.999
  Top Layer w0.152: v1(101.915,26.883) U7_S6.12@102.585,26.883
  Bottom Layer w0.15: v1(101.915,26.883) 101.915,25.425 102.191,25.149 102.583,25.149 105.58,22.152 111.153,22.152 111.8,22.799 111.8,25.141 114.822,28.162 116.775,28.162 117.737,27.2 117.737,23.026 117.387,22.676 117.387,18.211 125.2,10.399 v1(125.2,3.199)
COEX0: M1.52 P24.1 P27.1 R7.2 U7_S11.1 | length 97
  Top Layer w0.15: U7_S11.1@57.018,45.474 57.018,45.667 57.3,45.949 v2(58,45.949) ; v2(59.1,45.949) 60.043,45.949 62.343,48.249 63.08,48.249 66.9,52.069 v1(66.9,52.349) ; v1(90.4,49.749) 90.4,51.974 P24.1@91.766,53.34 ; M1.52@129.225,26.249 129.3,26.174 129.53,26.174 129.609,26.096 129.981,26.096 130.032,26.146 130.257,26.146 v1(130.324,26.213) 130.339,26.199 R7.2@130.915,26.199
  Mid-Layer 1 w0.15: v2(58,45.949) v2(59.1,45.949)
  Bottom Layer w0.15: v1(66.9,52.349) 67.559,51.69 87.495,51.69 89.436,49.749 v1(90.4,49.749) 91.054,49.095 103.808,49.095 108.829,44.074 110.814,44.074 122.106,32.782 127.32,32.782 130.45,29.652 130.45,28.486 cw(c130.3,28.486) 130.406,28.38 129.919,27.893 cw(c129.813,27.999) 129.813,27.849 129.712,27.849 ccw(c129.712,27.699) 129.606,27.805 129.348,27.547 ccw(c129.455,27.442) 129.305,27.442 129.305,26.4 129.609,26.096 130.112,26.096 130.23,26.213 v1(130.324,26.213)
  other v1: 93.027,53.34
COEX1: M1.53 P24.2 P27.2 U7_S11.5 | length 99.2
  Top Layer w0.15: U7_S11.5@55.193,45.249 55.193,46.142 v2(55.5,46.449) ; v2(59.1,46.449) 60.154,46.449 66.754,53.049 v1(66.836,53.049) ; v1(94.5,49.749) 94.567,49.816 94.866,49.816 95.254,50.204 95.254,52.392 96.202,53.34 v1(97.472,53.34) ; M1.53@129.225,26.749 129.3,26.749 129.375,26.674 129.572,26.674 129.7,26.546 v1(129.795,26.546)
  Mid-Layer 1 w0.15: v2(55.5,46.449) v2(59.1,46.449)
  Bottom Layer w0.15: v1(66.836,53.049) 67.92,51.965 87.798,51.965 89.564,50.199 90.586,50.199 91.036,49.749 v1(94.5,49.749) 94.513,49.749 94.513,49.736 94.879,49.37 103.922,49.37 108.943,44.349 110.928,44.349 122.22,33.057 127.434,33.057 130.725,29.766 130.725,28.299 130,27.574 129.842,27.574 129.58,27.311 129.58,26.856 129.795,26.64 v1(129.795,26.546)
COEX2: M1.54 P24.3 P27.3 R3.2 U7_S11.9 | length 99.4
  Top Layer w0.15: v2(55.805,42.824) 55.811,42.83 55.811,43.817 U7_S11.9@55.818,43.824 ; v2(56.6,42.361) 56.612,42.349 59.793,42.349 61.1,43.656 61.1,46.617 62.457,47.974 63.194,47.974 67.35,52.13 67.35,53.172 v1(66.773,53.749) ; M1.54@129.225,27.249 129.811,27.249 129.935,27.125 v1(130.03,27.125) 130.043,27.112 130.902,27.112 R3.2@130.915,27.099
  Mid-Layer 1 w0.15: v2(55.805,42.824) 56.239,42.39 56.571,42.39 v2(56.6,42.361)
  Bottom Layer w0.15: v1(66.773,53.749) 68.281,52.241 87.911,52.241 89.352,50.8 v1(93.027,50.8) 94.297,50.8 95.452,49.645 104.063,49.645 109.084,44.624 111.119,44.624 122.411,33.332 127.547,33.332 131,29.88 131,28.095 130.419,27.514 v1(130.03,27.125)
COEX_SELECT: R66.2 TP11.1 U3.AK14 U7_S11.2 U7_S11.10 | length 63.5
  Top Layer w0.125: v1(22.2,22.549) TP11.1@23,21.749 ; v1(31.436,20.549) 32.133,20.549 32.571,20.987 38.78,20.987 39.28,20.486 47.216,20.486 53.6,26.87 53.6,35.859 53.162,36.297 v2(53.162,36.349) ; v2(53.162,40.574) 52.63,40.574 52.4,40.804 52.4,41.224 52.5,41.324 54.85,41.324 56.145,42.619 56.145,42.776 56.218,42.849 U7_S11.10@56.218,43.824 56.218,44.067 56.618,44.467 U7_S11.2@56.618,45.474
  Mid-Layer 1 w0.125: v1(22.2,22.549) 22.937,23.286 23.769,23.286 24.325,23.842 24.325,25.346 v2@24.525,25.546 ; v2@24.49,25.581 24.525,25.616 v2(24.525,25.658) ; v2(53.162,36.349) v2(53.162,40.574)
  Bottom Layer w0.125: v1(22.2,22.549) 24.279,22.549 25.15,22.549 25.975,21.724 30.075,21.724 31.25,20.549 v1(31.436,20.549)
COM.CH1_S1: R11.2 TP3.1 U7_S1.16 | length 73
  Top Layer w0.125: R11.2@30.06,27.549 33.175,27.549 33.475,27.849 v1(33.475,27.874) ; v1(34.125,18.599) 33.875,18.849 33.22,18.849 TP3.1@33.02,19.049 33.957,19.986 38.366,19.986 40.491,17.861 44.887,17.861 44.972,17.946 46.09,17.946 54.6,26.456 54.6,36.034 54.862,36.297 v2(54.862,36.349) ; v2(54.862,40.549) 54.862,40.564 56.073,41.774 59.943,41.774 61.612,43.444 61.612,46.405 62.669,47.461 65.687,47.461 v2(66.025,47.124) ; U7_S1.16@66.025,45.249 v2(66.025,45.699)
  Mid-Layer 1 w0.125: v2(54.862,36.349) v2(54.862,40.549) v2@54.862,40.574 ; v2(66.025,45.699) v2(66.025,47.124)
  Bottom Layer w0.125: v1(33.475,27.874) 33.25,27.649 33.25,26.116 33.662,25.703 33.662,19.061 v1(34.125,18.599)
COM.CH1_S9: P28.2 P30.1 SB12.2 U8_S9.16 | length 26.5
  Top Layer w0.254: U8_S9.16@87.5,19.274 87.498,19.276 87.498,19.614 87.148,19.964 87.148,21.092 87.342,21.286 89.266,21.286 93.778,16.774 95.46,16.774 P28.2@95.46,15.699 95.46,14.864 96.088,14.236 101.942,14.236 103.353,12.824 104.73,12.824 P30.1@104.73,11.799 ; P30.1@105.237,12.927 105.237,13.548 105.688,13.999
COM.CH1_S11: P3.3 P9.3 U7_S11.16 | length 16.1
  Top Layer w0.15: U7_S11.16@57.643,45.249 58,45.249 58.42,45.669 P3.3@58.42,54.415 P3.3@58.42,57.345
  Bottom Layer w0.15: P9.3@58.42,53.823 P9.3@58.42,54.415 v1(58.42,55.88) P9.3@58.42,57.345
COM.CH2_S2: R16.2 TP10.1 U7_S2.4 | length 31.8
  Top Layer w0.125: R16.2@25.175,21.298 25.175,20.087 27.651,17.611 34.83,17.611 34.915,17.696 36.052,17.696 36.747,17.001 36.747,16.998 38.174,15.571 44.782,15.571 TP10.1@45.72,16.509 49.31,20.099 v2(49.45,20.099)
  Top Layer w0.15: U7_S2.4@50.8,19.324 50.8,19.649 v2(51.1,19.949)
  Mid-Layer 1 w0.15: v2(49.45,20.099) 50.95,20.099 v2(51.1,19.949)
COM.CH2_S11: P3.4 P9.4 U7_S11.4 | length 15.4
  Top Layer w0.15: U7_S11.4@55.818,45.474 55.818,45.874 55.88,45.936 P3.4@55.88,54.415 P3.4@55.88,57.345
  Bottom Layer w0.15: P9.4@55.88,53.823 P9.4@55.88,54.415 v1(55.88,55.88) P9.4@55.88,57.345
COM.CH3_S1: R12.2 TP7.1 U7_S1.8 | length 59.3
  Top Layer w0.125: R12.2@26.85,21.298 26.85,19.826 28.065,18.611 30.903,18.611 32.778,20.486 38.573,20.486 40.698,18.361 42.492,18.361 TP7.1@43.18,19.049 44.117,19.986 47.423,19.986 54.1,26.663 54.1,36.261 v2(54.012,36.349) ; v2(54.012,40.124) 55.4,40.124 56.55,41.274 60.15,41.274 62.2,43.324 v2(62.2,43.699) ; v2(62.9,44.051) 62.902,44.049 U7_S1.8@63.575,44.049
  Mid-Layer 1 w0.125: v2(54.012,36.349) v2(54.012,40.124) ; v2@62.175,43.674 v2(62.2,43.699) 62.552,44.051 v2(62.9,44.051)
COM.CH3_S4: U7_S4.8
COM.CH3_S11: P3.7 P9.7 U7_S11.8 | length 19.9
  Top Layer w0.15: P3.7@48.26,57.345 48.26,52.961 54.393,46.828 54.393,44.502 54.846,44.049 U7_S11.8@55.193,44.049
  Bottom Layer w0.15: P9.7@48.26,53.848 P9.7@48.26,54.415 P9.7@48.26,57.345
  other v1: 48.26,55.88
COM.CH4_S2: R15.2 TP6.1 U7_S2.12 | length 33.5
  Top Layer w0.125: R15.2@24.5,21.298 24.5,20.055 27.744,16.812 31.302,16.812 32.542,15.571 34.622,15.571 TP6.1@35.56,16.509 36.997,15.071 45.962,15.071 48.107,17.216 49.621,17.216 49.804,17.399 v2(50.2,17.399)
  Top Layer w0.15: v2(52,16.924) U7_S2.12@52,17.674
  Mid-Layer 1 w0.125: v2(50.2,17.399) 51.525,17.399 v2(52,16.924)
COM.CH4_S4: U7_S4.12
COM.CH4_S10: U7_S10.12
COM.CH4_S11: U7_S11.12
D:J6_N: J6.A7 J6.B7 TP19.1 U1.2 | length 6
  Top Layer w0.1: J6.A7@8.985,31.454 8.245,31.454 cw(c8.245,31.599) 8.1,31.599 8.1,32.299 cw(c8.2,32.299) 8.2,32.399 8.93,32.399 ccw(c8.93,32.454) J6.B7@8.985,32.454 10.145,32.454 10.2,32.399 v1@10.234,32.433 ; v1(10.232,32.435) v1@10.234,32.433 ; U1.2@11.1,32.449 11.093,32.442 10.267,32.442 10.255,32.454 v1@10.234,32.433
  Bottom Layer w0.1: v1@10.234,32.435 v1(10.232,32.435) TP19.1@11.074,33.275 TP19.1@11.074,33.275
D:J6_P: J6.A6 J6.B6 TP20.1 U1.3 | length 6.1
  Top Layer w0.1: J6.B6@8.985,30.954 9.655,30.954 9.8,31.099 v1(9.8,31.949) ; J6.A6@8.985,31.954 8.99,31.949 v1(9.8,31.949) ; U1.3@11.1,31.949 v1(9.8,31.949)
  Bottom Layer w0.1: v1(9.8,31.949) 10.393,31.949 TP20.1@11.582,30.759
D_N: U1.7 U3.B4 | length 11.3
  Top Layer w0.1: U1.7@12.1,32.449 12.3,32.449 12.35,32.399 12.35,32.383 12.409,32.324 21.9,32.324 cw(c21.9,31.774) 22.45,31.774 22.45,31.299 22.491,31.258 U3.B4@22.525,31.258
D_P: U1.6 U3.B2 | length 10.9
  Top Layer w0.1: U1.6@12.1,31.949 12.3,31.949 12.35,31.999 12.35,32.015 12.409,32.074 21.9,32.074 cw(c21.9,31.774) 22.2,31.774 22.2,31.299 22.159,31.258 U3.B2@22.125,31.258 U3.B2@22.12,31.258
DBG_CMD: J8.3 P25.8 SB11.1 | length 20.5
  Top Layer w0.15: v2(76.095,28.719) 80.595,28.719 81.125,29.249 SB11.1@83.65,29.249 83.688,29.249
  Mid-Layer 1 w0.15: v2(76.095,27.849) v2(76.095,28.719)
  Mid-Layer 2 w0.15: v1(76.095,20.374) v1(76.095,26.049)
  Bottom Layer w0.15: v1(76.095,20.374) 76.27,20.549 78.9,20.549 79.45,19.999 J8.3@79.45,17.469
DEC0: C6.1 M1.24 | length 2.2
  Top Layer w0.254: M1.24@120.35,20.374 120.35,19.249 120.6,18.999 C6.1@121.35,18.999
DECA: C40.2 U3.A13 | length 1.9
  Top Layer w0.225: U3.A13@24.325,31.658 C40.2@24.325,33.388 C40.2@24.325,33.563
DECN: C39.1 U3.A23 | length 1.2
  Top Layer w0.2: C39.1@26.159,32.758 26.159,32.299 26.325,32.133 U3.A23@26.325,31.658
DECR: C29.2 C30.1 U3.A27 U3.G31 | length 8.6
  Top Layer w0.2: U3.A27@27.125,31.658 27.125,32.001 27.806,32.683 28.35,32.683 v1(28.5,32.833) ; U3.G31@28.125,30.258 28.55,30.258 28.875,29.933 29.575,29.933 30.046,30.404 v1(30.046,30.842) ; v1@28.55,32.758 28.9,33.108 C29.2@28.9,33.508
  Bottom Layer w0.2: v1(28.5,32.833) 28.5,31.845 29.504,30.842 v1(30.046,30.842)
DECUSB: C38.1 U3.B6 | length 4.2
  Top Layer w0.187: C38.1@20.625,33.833 20.655,33.833 21.246,33.242 22.158,33.242 23.056,32.344 23.056,31.521 22.932,31.397 22.932,31.265 U3.B6@22.925,31.258 ; C38.1@20.925,33.833 C38.1@20.925,33.838
EXT_MEM_C\S\: U4.1 U7_S8.16 | length 11.5
  Top Layer w0.15: U4.1@77.282,34.529 77.282,34.216 77.939,33.56 85.636,33.56 86.273,34.197 86.273,35.176 U7_S8.16@85.8,35.649
EXT_MEM_CTRL: R38.2 U3.B14 U7_S8.2 U7_S8.10 | length 75.1
  Top Layer w0.125: v2(23.212,34.808) 23.212,36.399 23.812,36.999 26.375,36.999 27.15,36.224 43.225,36.224 v1(43.475,36.474)
  Top Layer w0.15: U7_S8.10@84.375,37.074 84.925,37.074 85.325,36.674 U7_S8.2@86.025,36.674 86.989,36.674 R38.2@87.003,36.66 87.003,35.802 v1(87,35.799)
  Mid-Layer 1 w0.125: v2(23.212,34.808) 23.212,34.745 24.262,33.696 24.262,31.521 v2(24.525,31.258)
  Bottom Layer w0.125: v1(43.475,36.474) 43.941,36.007 59.495,36.007 60.679,34.824 69.121,34.824 70.305,36.007 86.791,36.007 v1(87,35.799)
EXT_MEM_MISO: U4.2 U7_S8.12 | length 7.7
  Top Layer w0.15: U4.2@78.552,34.529 78.552,34.221 78.939,33.835 82.536,33.835 84.29,35.589 84.29,36.274 U7_S8.12@84.375,36.274
EXT_MEM_MOSI: U4.5 U7_S8.4 | length 9
  Top Layer w0.15: U4.5@81.092,42.269 81.092,41.095 82.064,40.124 84.745,40.124 86.65,38.219 86.65,37.929 86.195,37.474 U7_S8.4@86.025,37.474
EXT_MEM_SCK: U4.6 U7_S8.8 | length 7.3
  Top Layer w0.15: U4.6@79.822,42.269 79.822,41.976 81.95,39.849 83.925,39.849 84.6,39.174 U7_S8.8@84.6,38.099
FB2:VBUS: C51.2 FB2.2 J4.5 Q8.1 R76.1 R77.1 | length 56.9
  Top Layer w0.2: R77.1@1.45,18.234 R76.1@1.45,18.764 2.43,18.764 Q8.1@2.495,18.699
  Top Layer w0.3: v1(27.475,35.524) 33.85,35.524 35.525,33.849 35.525,30.649 J4.5@36.135,30.039
  Top Layer w0.4: Q8.1@2.495,18.699 2.495,22.309 cw(c5.035,22.309) 5.035,24.849 9.001,24.849 ccw(c9.001,25.449) 9.426,25.025 11.3,26.899 11.3,27.449 11.4,27.549 11.5,27.549 14.306,30.355 14.306,30.43 v1(14.325,30.449)
  Bottom Layer w0.3: v1(14.325,30.449) 14.325,38.674 14.65,38.999 19.35,38.999 22.825,35.524 v1(27.475,35.524)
